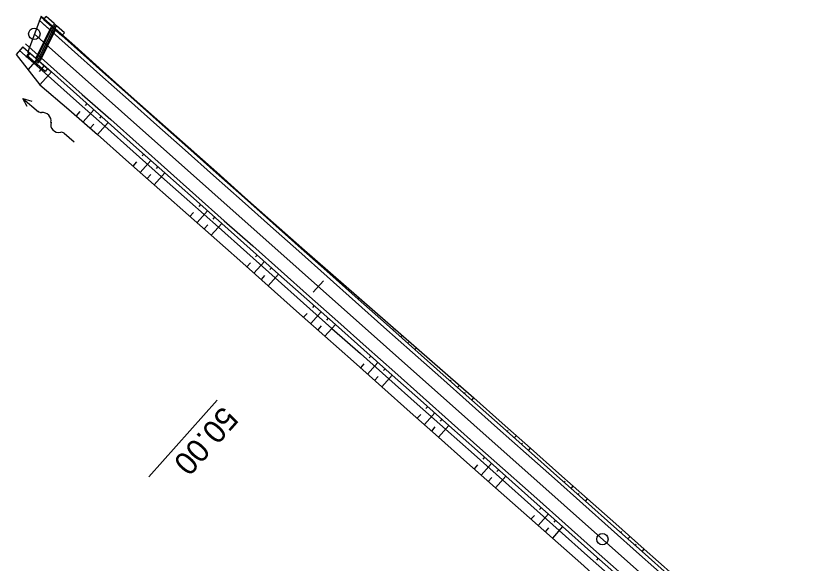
# Model space of a CAD drawing. Extents: x -481656 to -478728, y -1113199 to -1110710.
# Drawn here: x -480960.9 to -480855.1, y -1112648.7 to -1112576.6 of the extents above; entities that cross this region are included whole.
import ezdxf

# ---------------------------------------------------------------- set-up
doc = ezdxf.new("R2010")
doc.units = 0
for name, color, linetype in [('C13_HATCH_SLOPE_L', 7, 'Continuous'), ('C13_HATCH_SLOPE_R', 7, 'Continuous'), ('C13_HECTOMETRY', 7, 'Continuous'), ('C13_HLBODY', 7, 'Continuous'), ('C13_HRANA_TELESO', 7, 'Continuous'), ('C13_KORUNA', 7, 'Continuous'), ('C13_OSA', 7, 'Continuous'), ('C13_PRIKOP', 7, 'Continuous'), ('C13_STANICENI', 7, 'Continuous'), ('C13_VOZOVKA', 7, 'Continuous'), ('C13_ZPEVKRAJ', 7, 'Continuous'), ('DRENÁŽ', 7, 'Continuous'), ('PLYN', 7, 'Continuous'), ('ŽLAB', 7, 'Continuous')]:
    doc.layers.add(name, color=color, linetype=linetype)

# ---------------------------------------------------------------- blocks, each defined once
blk = doc.blocks.new('A$C70B')
at = {"layer": 'DRENÁŽ'}
for p, q in [((0.87, 0), (-0.87, 0)), ((6.86, 0.43), (7.97, 0)), ((7.97, 0), (5.28, 0)), ((7.97, 0), (6.86, -0.48))]:
    blk.add_line(p, q, dxfattribs=at)
for centre, radius, start, end in [((0.87, 0.58), 0.582, 269.6924, 322.7901), ((2.17, -0.42), 1.05, 24.4039, 142.0836), ((4.08, 0.59), 1.11, 210.8873, 317.3707), ((5.32, -0.64), 0.636, 85.9766, 131.7248)]:
    blk.add_arc(centre, radius, start, end, dxfattribs=at)

msp = doc.modelspace()

# ---------------------------------------------------------------- linework, layer by layer
at = {"layer": 'C13_HATCH_SLOPE_L'}
for p, q in [((-480957.02, -1112577.28), (-480956.96, -1112577.2)), ((-480956.09, -1112578.11), (-480956.05, -1112578.07)), ((-480955.16, -1112578.94), (-480955.08, -1112578.86)), ((-480954.22, -1112579.77), (-480954.18, -1112579.73)), ((-480953.29, -1112580.6), (-480953.21, -1112580.51)), ((-480948.62, -1112584.76), (-480948.59, -1112584.73)), ((-480948.57, -1112584.7), (-480948.57, -1112584.7)), ((-480947.69, -1112585.59), (-480947.63, -1112585.53)), ((-480946.75, -1112586.42), (-480946.73, -1112586.39)), ((-480946.7, -1112586.36), (-480946.7, -1112586.36)), ((-480945.82, -1112587.25), (-480945.77, -1112587.2)), ((-480941.15, -1112591.41), (-480941.12, -1112591.37)), ((-480941.09, -1112591.34), (-480941.09, -1112591.34)), ((-480940.22, -1112592.24), (-480940.15, -1112592.17)), ((-480939.28, -1112593.07), (-480939.25, -1112593.03)), ((-480939.21, -1112592.99), (-480939.21, -1112592.99)), ((-480938.35, -1112593.9), (-480938.27, -1112593.81)), ((-480933.68, -1112598.06), (-480933.65, -1112598.02)), ((-480933.61, -1112597.98), (-480933.61, -1112597.98)), ((-480932.75, -1112598.89), (-480932.68, -1112598.81)), ((-480931.81, -1112599.72), (-480931.78, -1112599.68)), ((-480931.75, -1112599.65), (-480931.75, -1112599.65)), ((-480930.88, -1112600.55), (-480930.82, -1112600.48)), ((-480926.21, -1112604.71), (-480926.19, -1112604.68)), ((-480926.16, -1112604.65), (-480926.16, -1112604.65)), ((-480925.28, -1112605.54), (-480925.22, -1112605.48)), ((-480924.29, -1112606.3), (-480924.29, -1112606.3)), ((-480924.35, -1112606.37), (-480924.32, -1112606.34)), ((-480923.41, -1112607.2), (-480923.35, -1112607.13)), ((-480918.74, -1112611.35), (-480918.69, -1112611.3)), ((-480918.64, -1112611.24), (-480918.64, -1112611.24)), ((-480917.81, -1112612.19), (-480917.7, -1112612.06)), ((-480916.88, -1112613.02), (-480916.82, -1112612.95)), ((-480916.76, -1112612.88), (-480916.76, -1112612.88)), ((-480915.94, -1112613.85), (-480915.81, -1112613.7)), ((-480911.27, -1112618), (-480911.19, -1112617.91)), ((-480911.1, -1112617.81), (-480911.1, -1112617.81)), ((-480910.34, -1112618.83), (-480910.16, -1112618.63)), ((-480909.41, -1112619.67), (-480909.31, -1112619.56)), ((-480909.22, -1112619.46), (-480909.22, -1112619.46)), ((-480908.47, -1112620.5), (-480908.28, -1112620.28)), ((-480903.8, -1112624.65), (-480903.69, -1112624.52)), ((-480903.57, -1112624.39), (-480903.57, -1112624.39)), ((-480902.87, -1112625.48), (-480902.63, -1112625.21)), ((-480901.94, -1112626.31), (-480901.81, -1112626.17)), ((-480901.68, -1112626.03), (-480901.68, -1112626.03)), ((-480901, -1112627.15), (-480900.74, -1112626.85)), ((-480896.33, -1112631.3), (-480896.2, -1112631.15)), ((-480896.06, -1112631), (-480896.06, -1112631)), ((-480895.4, -1112632.13), (-480895.13, -1112631.83)), ((-480894.2, -1112632.66), (-480894.2, -1112632.66)), ((-480894.47, -1112632.96), (-480894.33, -1112632.81)), ((-480893.53, -1112633.79), (-480893.26, -1112633.49)), ((-480888.86, -1112637.95), (-480888.73, -1112637.8)), ((-480888.59, -1112637.64), (-480888.59, -1112637.64)), ((-480887.93, -1112638.78), (-480887.66, -1112638.47)), ((-480887, -1112639.61), (-480886.86, -1112639.46)), ((-480886.72, -1112639.3), (-480886.72, -1112639.3)), ((-480886.06, -1112640.44), (-480885.79, -1112640.13)), ((-480881.11, -1112644.28), (-480881.11, -1112644.28)), ((-480881.4, -1112644.6), (-480881.26, -1112644.44)), ((-480880.46, -1112645.43), (-480880.18, -1112645.11)), ((-480879.53, -1112646.26), (-480879.39, -1112646.1)), ((-480879.24, -1112645.94), (-480879.24, -1112645.94)), ((-480878.59, -1112647.09), (-480878.31, -1112646.77))]:
    msp.add_line(p, q, dxfattribs=at)
at = {"layer": 'C13_HATCH_SLOPE_R'}
for p, q in [((-480960.02, -1112580.64), (-480960.92, -1112581.65)), ((-480959.08, -1112581.47), (-480959.61, -1112582.06)), ((-480958.15, -1112582.3), (-480959.35, -1112583.65)), ((-480957.22, -1112583.13), (-480957.89, -1112583.89)), ((-480956.28, -1112583.97), (-480957.78, -1112585.64)), ((-480951.61, -1112588.12), (-480951.83, -1112588.37)), ((-480952.55, -1112589.17), (-480953.04, -1112589.72)), ((-480950.68, -1112588.95), (-480952.1, -1112590.55)), ((-480949.74, -1112589.78), (-480949.97, -1112590.03)), ((-480950.68, -1112590.83), (-480951.17, -1112591.38)), ((-480948.81, -1112590.61), (-480950.23, -1112592.21)), ((-480943.21, -1112595.6), (-480944.61, -1112597.18)), ((-480944.14, -1112594.77), (-480944.36, -1112595.02)), ((-480945.07, -1112595.81), (-480945.55, -1112596.35)), ((-480942.28, -1112596.43), (-480942.5, -1112596.68)), ((-480943.2, -1112597.47), (-480943.68, -1112598.01)), ((-480941.34, -1112597.26), (-480942.74, -1112598.84)), ((-480936.67, -1112601.42), (-480936.9, -1112601.67)), ((-480937.59, -1112602.45), (-480938.06, -1112602.98)), ((-480935.74, -1112602.25), (-480937.12, -1112603.8)), ((-480934.81, -1112603.08), (-480935.03, -1112603.33)), ((-480935.72, -1112604.1), (-480936.19, -1112604.63)), ((-480933.87, -1112603.91), (-480935.25, -1112605.46)), ((-480929.2, -1112608.07), (-480929.43, -1112608.32)), ((-480930.11, -1112609.08), (-480930.57, -1112609.6)), ((-480928.27, -1112608.9), (-480929.64, -1112610.44)), ((-480927.34, -1112609.73), (-480927.56, -1112609.98)), ((-480928.24, -1112610.75), (-480928.71, -1112611.27)), ((-480926.4, -1112610.56), (-480927.78, -1112612.1)), ((-480921.73, -1112614.72), (-480921.96, -1112614.96)), ((-480922.64, -1112615.74), (-480923.11, -1112616.26)), ((-480920.8, -1112615.55), (-480922.18, -1112617.09)), ((-480919.87, -1112616.38), (-480920.09, -1112616.63)), ((-480920.78, -1112617.4), (-480921.24, -1112617.92)), ((-480918.93, -1112617.21), (-480920.31, -1112618.75)), ((-480914.27, -1112621.36), (-480914.49, -1112621.61)), ((-480915.17, -1112622.38), (-480915.64, -1112622.91)), ((-480913.33, -1112622.2), (-480914.7, -1112623.74)), ((-480912.4, -1112623.03), (-480912.62, -1112623.27)), ((-480913.31, -1112624.05), (-480913.77, -1112624.57)), ((-480911.46, -1112623.86), (-480912.84, -1112625.4)), ((-480906.79, -1112628.01), (-480907.02, -1112628.26)), ((-480907.7, -1112629.03), (-480908.17, -1112629.55)), ((-480905.86, -1112628.84), (-480907.23, -1112630.38)), ((-480903.99, -1112630.51), (-480905.36, -1112632.05)), ((-480904.93, -1112629.68), (-480905.15, -1112629.92)), ((-480905.84, -1112630.69), (-480906.3, -1112631.22)), ((-480899.33, -1112634.66), (-480899.55, -1112634.91)), ((-480900.23, -1112635.68), (-480900.7, -1112636.2)), ((-480898.39, -1112635.49), (-480899.76, -1112637.03)), ((-480897.46, -1112636.32), (-480897.68, -1112636.57)), ((-480898.36, -1112637.34), (-480898.83, -1112637.86)), ((-480896.53, -1112637.16), (-480897.89, -1112638.69)), ((-480890.92, -1112642.14), (-480892.27, -1112643.66)), ((-480891.86, -1112641.31), (-480892.08, -1112641.56)), ((-480892.75, -1112642.32), (-480893.21, -1112642.83)), ((-480889.99, -1112642.97), (-480890.21, -1112643.22)), ((-480890.89, -1112643.98), (-480891.34, -1112644.49)), ((-480889.05, -1112643.8), (-480890.4, -1112645.32)), ((-480884.39, -1112647.96), (-480884.61, -1112648.21))]:
    msp.add_line(p, q, dxfattribs=at)
at = {"layer": 'C13_HECTOMETRY'}
for centre in [(-480958.52, -1112578.96), (-480883.82, -1112645.45)]:
    msp.add_circle(centre, 0.75, dxfattribs=at)
at = {"layer": 'C13_HLBODY'}
msp.add_circle((-480958.52, -1112578.96), 0.75, dxfattribs=at)
at = {"layer": 'C13_HRANA_TELESO'}
for p, q in [((-480957.63, -1112576.61), (-480959.4, -1112581.47)), ((-480957.63, -1112576.61), (-480953.21, -1112580.51)), ((-480953.21, -1112580.51), (-480949.5, -1112583.86)), ((-480960.92, -1112581.65), (-480957.78, -1112585.64)), ((-480949.5, -1112583.86), (-480945.77, -1112587.2)), ((-480957.78, -1112585.64), (-480953.97, -1112588.89)), ((-480945.77, -1112587.2), (-480942.03, -1112590.52)), ((-480953.97, -1112588.89), (-480950.23, -1112592.21)), ((-480942.03, -1112590.52), (-480938.27, -1112593.81)), ((-480950.23, -1112592.21), (-480946.49, -1112595.52)), ((-480938.27, -1112593.81), (-480934.54, -1112597.14)), ((-480946.49, -1112595.52), (-480942.74, -1112598.84)), ((-480934.54, -1112597.14), (-480930.82, -1112600.48)), ((-480942.74, -1112598.84), (-480939, -1112602.15)), ((-480930.82, -1112600.48), (-480927.09, -1112603.82)), ((-480939, -1112602.15), (-480935.25, -1112605.46)), ((-480927.09, -1112603.82), (-480923.35, -1112607.13)), ((-480935.25, -1112605.46), (-480931.51, -1112608.77)), ((-480923.35, -1112607.13), (-480919.58, -1112610.42)), ((-480931.51, -1112608.77), (-480927.78, -1112612.1)), ((-480919.58, -1112610.42), (-480915.81, -1112613.7)), ((-480927.78, -1112612.1), (-480924.04, -1112615.43)), ((-480915.81, -1112613.7), (-480912.04, -1112616.99)), ((-480924.04, -1112615.43), (-480920.31, -1112618.75)), ((-480912.04, -1112616.99), (-480908.28, -1112620.28)), ((-480920.31, -1112618.75), (-480916.57, -1112622.08)), ((-480908.28, -1112620.28), (-480904.51, -1112623.56)), ((-480916.57, -1112622.08), (-480912.84, -1112625.4)), ((-480904.51, -1112623.56), (-480900.74, -1112626.85)), ((-480912.84, -1112625.4), (-480909.1, -1112628.72)), ((-480900.74, -1112626.85), (-480897, -1112630.17)), ((-480909.1, -1112628.72), (-480905.36, -1112632.05)), ((-480897, -1112630.17), (-480893.26, -1112633.49)), ((-480905.36, -1112632.05), (-480901.63, -1112635.37)), ((-480893.26, -1112633.49), (-480889.53, -1112636.81)), ((-480901.63, -1112635.37), (-480897.89, -1112638.69)), ((-480889.53, -1112636.81), (-480885.79, -1112640.13)), ((-480897.89, -1112638.69), (-480894.14, -1112642)), ((-480885.79, -1112640.13), (-480882.05, -1112643.45)), ((-480894.14, -1112642), (-480890.4, -1112645.32)), ((-480882.05, -1112643.45), (-480878.31, -1112646.77)), ((-480890.4, -1112645.32), (-480886.66, -1112648.63)), ((-480878.31, -1112646.77), (-480874.57, -1112650.09)), ((-480886.66, -1112648.63), (-480882.92, -1112651.95))]:
    msp.add_line(p, q, dxfattribs=at)
at = {"layer": 'C13_KORUNA'}
for p, q in [((-480957.67, -1112576.7), (-480953.29, -1112580.6)), ((-480960.02, -1112580.64), (-480956.28, -1112583.97)), ((-480953.29, -1112580.6), (-480949.55, -1112583.93)), ((-480956.28, -1112583.97), (-480952.55, -1112587.29)), ((-480949.55, -1112583.93), (-480945.82, -1112587.25)), ((-480945.82, -1112587.25), (-480942.09, -1112590.58)), ((-480952.55, -1112587.29), (-480948.81, -1112590.61)), ((-480948.81, -1112590.61), (-480945.08, -1112593.94)), ((-480942.09, -1112590.58), (-480938.35, -1112593.9)), ((-480945.08, -1112593.94), (-480941.34, -1112597.26)), ((-480938.35, -1112593.9), (-480934.61, -1112597.23)), ((-480941.34, -1112597.26), (-480937.61, -1112600.59)), ((-480934.61, -1112597.23), (-480930.88, -1112600.55)), ((-480937.61, -1112600.59), (-480933.87, -1112603.91)), ((-480930.88, -1112600.55), (-480927.15, -1112603.87)), ((-480933.87, -1112603.91), (-480930.14, -1112607.24)), ((-480927.15, -1112603.87), (-480923.41, -1112607.2)), ((-480930.14, -1112607.24), (-480926.4, -1112610.56)), ((-480923.41, -1112607.2), (-480919.68, -1112610.52)), ((-480919.68, -1112610.52), (-480915.94, -1112613.85)), ((-480926.4, -1112610.56), (-480922.67, -1112613.88)), ((-480922.67, -1112613.88), (-480918.93, -1112617.21)), ((-480915.94, -1112613.85), (-480912.21, -1112617.17)), ((-480918.93, -1112617.21), (-480915.2, -1112620.53)), ((-480912.21, -1112617.17), (-480908.47, -1112620.5)), ((-480915.2, -1112620.53), (-480911.46, -1112623.86)), ((-480908.47, -1112620.5), (-480904.74, -1112623.82)), ((-480911.46, -1112623.86), (-480907.73, -1112627.18)), ((-480904.74, -1112623.82), (-480901, -1112627.15)), ((-480907.73, -1112627.18), (-480903.99, -1112630.51)), ((-480901, -1112627.15), (-480897.27, -1112630.47)), ((-480903.99, -1112630.51), (-480900.26, -1112633.83)), ((-480897.27, -1112630.47), (-480893.53, -1112633.79)), ((-480893.53, -1112633.79), (-480889.8, -1112637.12)), ((-480900.26, -1112633.83), (-480896.53, -1112637.16)), ((-480896.53, -1112637.16), (-480892.79, -1112640.48)), ((-480889.8, -1112637.12), (-480886.06, -1112640.44)), ((-480892.79, -1112640.48), (-480889.05, -1112643.8)), ((-480886.06, -1112640.44), (-480882.33, -1112643.77)), ((-480889.05, -1112643.8), (-480885.32, -1112647.13)), ((-480882.33, -1112643.77), (-480878.59, -1112647.09)), ((-480885.32, -1112647.13), (-480881.59, -1112650.45)), ((-480878.59, -1112647.09), (-480874.86, -1112650.42))]:
    msp.add_line(p, q, dxfattribs=at)
at = {"layer": 'C13_OSA'}
msp.add_line((-480958.52, -1112578.96), (-480855.08, -1112671.03), dxfattribs=at)
at = {"layer": 'C13_PRIKOP'}
for p, q in [((-480960.46, -1112581.14), (-480956.72, -1112584.46)), ((-480956.72, -1112584.46), (-480952.99, -1112587.79)), ((-480952.99, -1112587.79), (-480949.26, -1112591.11)), ((-480949.26, -1112591.11), (-480945.52, -1112594.44)), ((-480945.52, -1112594.44), (-480941.79, -1112597.76)), ((-480941.79, -1112597.76), (-480938.05, -1112601.08)), ((-480938.05, -1112601.08), (-480934.32, -1112604.41)), ((-480934.32, -1112604.41), (-480930.58, -1112607.73)), ((-480930.58, -1112607.73), (-480926.85, -1112611.06)), ((-480926.85, -1112611.06), (-480923.11, -1112614.38)), ((-480923.11, -1112614.38), (-480919.38, -1112617.71)), ((-480919.38, -1112617.71), (-480915.64, -1112621.03)), ((-480915.64, -1112621.03), (-480911.91, -1112624.35)), ((-480911.91, -1112624.35), (-480908.17, -1112627.68)), ((-480908.17, -1112627.68), (-480904.44, -1112631)), ((-480904.44, -1112631), (-480900.7, -1112634.33)), ((-480900.7, -1112634.33), (-480896.97, -1112637.65)), ((-480896.97, -1112637.65), (-480893.23, -1112640.98)), ((-480893.23, -1112640.98), (-480889.5, -1112644.3)), ((-480889.5, -1112644.3), (-480885.76, -1112647.63)), ((-480885.76, -1112647.63), (-480882.03, -1112650.95))]:
    msp.add_line(p, q, dxfattribs=at)
at = {"layer": 'C13_STANICENI'}
for p, q in [((-480921.84, -1112612.95), (-480920.51, -1112611.46)), ((-480934.47, -1112627.14), (-480943.45, -1112637.23))]:
    msp.add_line(p, q, dxfattribs=at)
at = {"layer": 'C13_VOZOVKA'}
for p, q in [((-480957.9, -1112577.17), (-480953.62, -1112580.98)), ((-480959.68, -1112580.27), (-480955.95, -1112583.59)), ((-480953.62, -1112580.98), (-480949.89, -1112584.3)), ((-480955.95, -1112583.59), (-480952.21, -1112586.92)), ((-480949.89, -1112584.3), (-480946.15, -1112587.63)), ((-480952.21, -1112586.92), (-480948.48, -1112590.24)), ((-480946.15, -1112587.63), (-480942.42, -1112590.95)), ((-480948.48, -1112590.24), (-480944.74, -1112593.56)), ((-480942.42, -1112590.95), (-480938.68, -1112594.27)), ((-480944.74, -1112593.56), (-480941.01, -1112596.89)), ((-480938.68, -1112594.27), (-480934.95, -1112597.6)), ((-480941.01, -1112596.89), (-480937.28, -1112600.21)), ((-480934.95, -1112597.6), (-480931.21, -1112600.92)), ((-480937.28, -1112600.21), (-480933.54, -1112603.54)), ((-480931.21, -1112600.92), (-480927.48, -1112604.25)), ((-480933.54, -1112603.54), (-480929.8, -1112606.86)), ((-480927.48, -1112604.25), (-480923.74, -1112607.57)), ((-480929.8, -1112606.86), (-480926.07, -1112610.19)), ((-480923.74, -1112607.57), (-480920.01, -1112610.9)), ((-480926.07, -1112610.19), (-480922.34, -1112613.51)), ((-480920.01, -1112610.9), (-480916.27, -1112614.22)), ((-480922.34, -1112613.51), (-480918.6, -1112616.83)), ((-480916.27, -1112614.22), (-480912.54, -1112617.54)), ((-480918.6, -1112616.83), (-480914.87, -1112620.16)), ((-480912.54, -1112617.54), (-480908.8, -1112620.87)), ((-480914.87, -1112620.16), (-480911.13, -1112623.48)), ((-480908.8, -1112620.87), (-480905.07, -1112624.19)), ((-480911.13, -1112623.48), (-480907.4, -1112626.81)), ((-480905.07, -1112624.19), (-480901.34, -1112627.52)), ((-480907.4, -1112626.81), (-480903.66, -1112630.13)), ((-480901.34, -1112627.52), (-480897.6, -1112630.84)), ((-480903.66, -1112630.13), (-480899.93, -1112633.46)), ((-480897.6, -1112630.84), (-480893.86, -1112634.17)), ((-480899.93, -1112633.46), (-480896.19, -1112636.78)), ((-480893.86, -1112634.17), (-480890.13, -1112637.49)), ((-480896.19, -1112636.78), (-480892.46, -1112640.11)), ((-480890.13, -1112637.49), (-480886.4, -1112640.82)), ((-480892.46, -1112640.11), (-480888.72, -1112643.43)), ((-480886.4, -1112640.82), (-480882.66, -1112644.14)), ((-480888.72, -1112643.43), (-480884.99, -1112646.76)), ((-480882.66, -1112644.14), (-480878.93, -1112647.47)), ((-480884.99, -1112646.76), (-480881.25, -1112650.08)), ((-480878.93, -1112647.47), (-480875.19, -1112650.79))]:
    msp.add_line(p, q, dxfattribs=at)
at = {"layer": 'C13_ZPEVKRAJ'}
for p, q in [((-480957.36, -1112577.65), (-480953.62, -1112580.98)), ((-480959.68, -1112580.27), (-480955.95, -1112583.59)), ((-480953.62, -1112580.98), (-480949.89, -1112584.3)), ((-480955.95, -1112583.59), (-480952.21, -1112586.92)), ((-480949.89, -1112584.3), (-480946.15, -1112587.63)), ((-480952.21, -1112586.92), (-480948.48, -1112590.24)), ((-480946.15, -1112587.63), (-480942.42, -1112590.95)), ((-480948.48, -1112590.24), (-480944.74, -1112593.56)), ((-480942.42, -1112590.95), (-480938.68, -1112594.27)), ((-480944.74, -1112593.56), (-480941.01, -1112596.89)), ((-480938.68, -1112594.27), (-480934.95, -1112597.6)), ((-480941.01, -1112596.89), (-480937.28, -1112600.21)), ((-480934.95, -1112597.6), (-480931.21, -1112600.92)), ((-480937.28, -1112600.21), (-480933.54, -1112603.54)), ((-480931.21, -1112600.92), (-480927.48, -1112604.25)), ((-480933.54, -1112603.54), (-480929.8, -1112606.86)), ((-480927.48, -1112604.25), (-480923.74, -1112607.57)), ((-480929.8, -1112606.86), (-480926.07, -1112610.19)), ((-480923.74, -1112607.57), (-480920.01, -1112610.9)), ((-480926.07, -1112610.19), (-480922.34, -1112613.51)), ((-480920.01, -1112610.9), (-480916.27, -1112614.22)), ((-480922.34, -1112613.51), (-480918.6, -1112616.83)), ((-480916.27, -1112614.22), (-480912.54, -1112617.54)), ((-480918.6, -1112616.83), (-480914.87, -1112620.16)), ((-480912.54, -1112617.54), (-480908.8, -1112620.87)), ((-480914.87, -1112620.16), (-480911.13, -1112623.48)), ((-480908.8, -1112620.87), (-480905.07, -1112624.19)), ((-480911.13, -1112623.48), (-480907.4, -1112626.81)), ((-480905.07, -1112624.19), (-480901.34, -1112627.52)), ((-480907.4, -1112626.81), (-480903.66, -1112630.13)), ((-480901.34, -1112627.52), (-480897.6, -1112630.84)), ((-480903.66, -1112630.13), (-480899.93, -1112633.46)), ((-480897.6, -1112630.84), (-480893.86, -1112634.17)), ((-480899.93, -1112633.46), (-480896.19, -1112636.78)), ((-480893.86, -1112634.17), (-480890.13, -1112637.49)), ((-480896.19, -1112636.78), (-480892.46, -1112640.11)), ((-480890.13, -1112637.49), (-480886.4, -1112640.82)), ((-480892.46, -1112640.11), (-480888.72, -1112643.43)), ((-480886.4, -1112640.82), (-480882.66, -1112644.14)), ((-480888.72, -1112643.43), (-480884.99, -1112646.76)), ((-480882.66, -1112644.14), (-480878.93, -1112647.47)), ((-480884.99, -1112646.76), (-480881.25, -1112650.08)), ((-480878.93, -1112647.47), (-480875.19, -1112650.79))]:
    msp.add_line(p, q, dxfattribs=at)
at = {"layer": 'ŽLAB'}
for p, q in [((-480957.29, -1112577.06), (-480956.96, -1112576.69)), ((-480957.29, -1112577.06), (-480956.24, -1112577.99)), ((-480955.91, -1112577.61), (-480956.96, -1112576.69)), ((-480955.99, -1112577.72), (-480956.43, -1112578.62)), ((-480955.61, -1112577.88), (-480955.91, -1112577.61)), ((-480958.42, -1112582.69), (-480956.21, -1112578.17)), ((-480956.35, -1112578.1), (-480958.33, -1112582.17)), ((-480955.82, -1112577.81), (-480958.24, -1112582.77)), ((-480955.64, -1112577.89), (-480958.06, -1112582.86)), ((-480957.7, -1112582.48), (-480955.72, -1112578.41)), ((-480955.85, -1112578.34), (-480956.21, -1112578.17)), ((-480955.64, -1112577.89), (-480956.07, -1112578.79)), ((-480955.94, -1112578.25), (-480954.89, -1112579.18)), ((-480954.56, -1112578.8), (-480955.61, -1112577.88)), ((-480954.89, -1112579.18), (-480954.56, -1112578.8)), ((-480959.18, -1112581.42), (-480959.51, -1112581.8)), ((-480958.45, -1112582.72), (-480959.51, -1112581.8)), ((-480959.18, -1112581.42), (-480958.12, -1112582.34)), ((-480958.15, -1112582.99), (-480958.45, -1112582.72)), ((-480958.2, -1112582.24), (-480958.42, -1112582.69)), ((-480957.1, -1112583.91), (-480958.15, -1112582.99)), ((-480957.84, -1112582.41), (-480958.06, -1112582.86)), ((-480957.82, -1112582.61), (-480956.77, -1112583.53)), ((-480956.77, -1112583.53), (-480957.1, -1112583.91))]:
    msp.add_line(p, q, dxfattribs=at)

# ---------------------------------------------------------------- block references
at = {"layer": 'PLYN', "rotation": 139.82273357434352}
msp.add_blockref('A$C70B', (-480953.93, -1112592.6), dxfattribs=at)

# ---------------------------------------------------------------- texts
at = {"layer": 'C13_STANICENI'}
msp.add_text('50.00', height=3, rotation=228.3273, dxfattribs=at).set_placement((-480933.72, -1112627.81))

doc.saveas('drawing.dxf')
